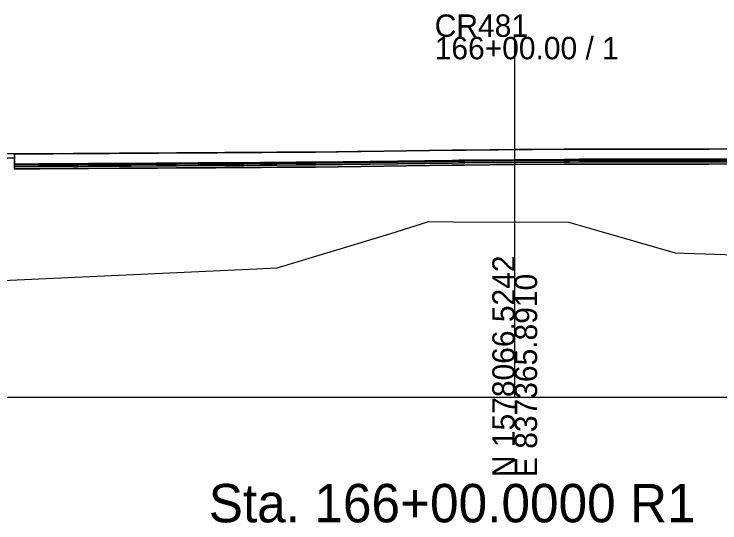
# Model space of a CAD drawing. Extents: x -26 to 303, y -16 to 6048.
# Drawn here: x 87.4 to 175.6, y 5984.3 to 6047.8 of the extents above; entities that cross this region are included whole.
import ezdxf

# ---------------------------------------------------------------- set-up
doc = ezdxf.new("R2010")
doc.units = 0
for name, color, linetype in [('ASPHALT_19MM1', 7, 'Continuous'), ('ASPHALT_9_5MM1', 7, 'Continuous'), ('CONST_LV3', 7, 'Continuous'), ('Default', 7, 'Continuous'), ('Draft_XS_Text', 7, 'Continuous'), ('DTM_P_FINISHED_GRADE', 7, 'Continuous'), ('DTM_P_FINISHED_GRADE2', 7, 'Continuous'), ('DTM_X_GROUND', 7, 'Continuous'), ('TRANS_PAVED_SHOULDERS', 7, 'Continuous'), ('XS_CELL', 7, 'Continuous'), ('XS_M_SHAPES_EARTHWORK', 7, 'Continuous'), ('XS_P_ASPHALT', 7, 'Continuous'), ('XS_P_SUBGRADE_GRANULAR', 7, 'Continuous')]:
    doc.layers.add(name, color=color, linetype=linetype)

msp = doc.modelspace()

# ---------------------------------------------------------------- linework, layer by layer
at = {"layer": 'ASPHALT_19MM1'}
for points in [[(90.504, 6028.792), (87.441, 6028.775), (87.441, 6028.504), (90.504, 6028.521), (90.558, 6028.522), (90.706, 6028.523), (94.869, 6028.545), (95.459, 6028.549), (96.738, 6028.558), (100.596, 6028.579), (102.069, 6028.589), (105.237, 6028.606), (105.365, 6028.607), (107.722, 6028.624), (110.43, 6028.639), (111.485, 6028.646), (111.83, 6028.649), (112.658, 6028.655), (113.784, 6028.663), (116.149, 6028.676), (118.218, 6028.692), (118.344, 6028.693), (120.279, 6028.703), (122.675, 6028.722), (122.886, 6028.723), (125.089, 6028.741), (142.197, 6028.968), (142.997, 6028.974), (143.099, 6028.975), (143.136, 6028.975), (143.744, 6028.98), (150, 6029.046), (156.166, 6029.08), (156.838, 6029.086), (158.11, 6029.096), (158.562, 6029.1), (159.52, 6029.106), (174.235, 6029.102), (176.786, 6029.125)], [(176.786, 6029.396), (174.235, 6029.373), (159.52, 6029.377), (158.562, 6029.371), (158.11, 6029.367), (156.838, 6029.356), (156.166, 6029.351), (150, 6029.316), (143.744, 6029.251), (143.136, 6029.246), (143.099, 6029.246), (142.997, 6029.245), (142.197, 6029.239), (125.089, 6029.011), (122.886, 6028.994), (122.675, 6028.993), (120.279, 6028.974), (118.344, 6028.964), (118.218, 6028.963), (116.149, 6028.947), (113.784, 6028.934), (112.658, 6028.926), (111.83, 6028.92), (111.485, 6028.917), (110.43, 6028.909), (107.722, 6028.895), (105.365, 6028.878), (105.237, 6028.877), (102.069, 6028.86), (100.596, 6028.849), (96.738, 6028.828), (95.459, 6028.82), (94.869, 6028.816), (90.706, 6028.793), (90.558, 6028.792), (90.504, 6028.792)]]:
    msp.add_lwpolyline(points, dxfattribs=at)
at = {"layer": 'ASPHALT_9_5MM1'}
for points in [[(90.504, 6029.125), (87.441, 6029.109), (87.441, 6028.984), (90.504, 6029), (90.558, 6029.001), (90.706, 6029.002), (94.869, 6029.024), (95.459, 6029.028), (96.738, 6029.037), (100.596, 6029.058), (102.069, 6029.068), (105.237, 6029.085), (105.365, 6029.086), (107.722, 6029.103), (110.43, 6029.118), (111.485, 6029.125), (111.83, 6029.128), (112.658, 6029.134), (113.784, 6029.143), (116.149, 6029.155), (118.218, 6029.171), (118.344, 6029.172), (120.279, 6029.182), (122.675, 6029.201), (122.886, 6029.203), (125.089, 6029.22), (142.197, 6029.447), (142.997, 6029.453), (143.099, 6029.454), (143.136, 6029.454), (143.744, 6029.459), (150, 6029.525), (156.166, 6029.559), (156.838, 6029.565), (158.11, 6029.576), (158.562, 6029.58), (159.52, 6029.586), (174.235, 6029.582), (176.786, 6029.605)], [(176.786, 6029.73), (174.235, 6029.707), (159.52, 6029.711), (158.562, 6029.705), (158.11, 6029.701), (156.838, 6029.69), (156.166, 6029.684), (150, 6029.65), (143.744, 6029.584), (143.136, 6029.579), (143.099, 6029.579), (142.997, 6029.578), (142.197, 6029.572), (125.089, 6029.345), (122.886, 6029.328), (122.675, 6029.326), (120.279, 6029.307), (118.344, 6029.297), (118.218, 6029.296), (116.149, 6029.28), (113.784, 6029.268), (112.658, 6029.259), (111.83, 6029.253), (111.485, 6029.25), (110.43, 6029.243), (107.722, 6029.228), (105.365, 6029.211), (105.237, 6029.21), (102.069, 6029.193), (100.596, 6029.183), (96.738, 6029.162), (95.459, 6029.153), (94.869, 6029.149), (90.706, 6029.127), (90.558, 6029.126), (90.504, 6029.125)]]:
    msp.add_lwpolyline(points, dxfattribs=at)
at = {"layer": 'CONST_LV3'}
for points in [[(176.786, 6031), (174.235, 6030.977), (159.52, 6030.981), (158.562, 6030.975), (158.11, 6030.971), (156.838, 6030.961), (156.166, 6030.955), (150, 6030.921), (143.744, 6030.855), (143.136, 6030.85), (143.099, 6030.85), (142.997, 6030.849), (142.197, 6030.843), (125.089, 6030.616), (122.886, 6030.598), (122.675, 6030.597), (120.279, 6030.578), (118.344, 6030.568), (118.218, 6030.567), (116.149, 6030.551), (113.784, 6030.538), (112.658, 6030.53), (111.83, 6030.524), (111.485, 6030.521), (110.43, 6030.514), (107.722, 6030.499), (105.365, 6030.482), (105.237, 6030.481), (102.069, 6030.464), (100.596, 6030.454), (96.738, 6030.433), (95.459, 6030.424), (94.869, 6030.42), (90.706, 6030.398), (90.558, 6030.397), (90.504, 6030.396)], [(85.645, 6029.871), (87.542, 6029.879), (87.542, 6030.379), (85.645, 6030.371)], [(90.504, 6030.396), (87.441, 6030.379), (87.441, 6029.109), (90.504, 6029.125), (90.558, 6029.126), (90.706, 6029.127), (94.869, 6029.149), (95.459, 6029.153), (96.738, 6029.162), (100.596, 6029.183), (102.069, 6029.193), (105.237, 6029.21), (105.365, 6029.211), (107.722, 6029.228), (110.43, 6029.243), (111.485, 6029.25), (111.83, 6029.253), (112.658, 6029.259), (113.784, 6029.268), (116.149, 6029.28), (118.218, 6029.296), (118.344, 6029.297), (120.279, 6029.307), (122.675, 6029.326), (122.886, 6029.328), (125.089, 6029.345), (142.197, 6029.572), (142.997, 6029.578), (143.099, 6029.579), (143.136, 6029.579), (143.744, 6029.584), (150, 6029.65), (156.166, 6029.684), (156.838, 6029.69), (158.11, 6029.701), (158.562, 6029.705), (159.52, 6029.711), (174.235, 6029.707), (176.786, 6029.73)]]:
    msp.add_lwpolyline(points, dxfattribs=at)
at = {"layer": 'Default'}
for points in [[(87.542, 6030.379), (87.745, 6030.38), (87.819, 6030.38), (90.048, 6030.394), (90.443, 6030.397), (90.459, 6030.397), (90.474, 6030.397), (90.599, 6030.397), (90.861, 6030.399), (91.006, 6030.399), (92.34, 6030.406), (93.426, 6030.412), (94.869, 6030.421), (95.463, 6030.425), (95.475, 6030.425), (95.58, 6030.425), (95.691, 6030.425), (96.854, 6030.431), (97.827, 6030.436), (99.347, 6030.447), (100.357, 6030.453), (100.367, 6030.453), (100.454, 6030.453), (102.194, 6030.465), (102.3, 6030.466), (102.982, 6030.47), (104.554, 6030.478), (105.244, 6030.483), (105.372, 6030.484), (105.456, 6030.483), (105.534, 6030.484), (108.837, 6030.508), (109.359, 6030.511), (109.788, 6030.513), (110.274, 6030.516), (111.486, 6030.523), (111.831, 6030.526), (111.839, 6030.526), (111.847, 6030.526), (111.915, 6030.525), (112.747, 6030.532), (112.822, 6030.532), (113.955, 6030.54), (114.332, 6030.542), (115.782, 6030.55), (116.154, 6030.553), (118.349, 6030.569), (118.356, 6030.569), (118.417, 6030.569), (118.481, 6030.57), (119.678, 6030.576), (119.964, 6030.577), (120.012, 6030.578), (122.122, 6030.594), (122.409, 6030.596), (122.675, 6030.598), (122.887, 6030.6), (122.944, 6030.599), (125.154, 6030.617), (125.21, 6030.617), (125.427, 6030.618), (129.568, 6030.674), (129.788, 6030.675), (129.793, 6030.676), (129.798, 6030.676), (129.844, 6030.676), (129.891, 6030.676), (130.054, 6030.677), (133.499, 6030.729), (134.843, 6030.747), (141.853, 6030.841), (142.405, 6030.846), (143.179, 6030.852), (143.279, 6030.853), (143.905, 6030.858), (147.923, 6030.9), (150, 6030.921), (152.201, 6030.934), (156.7, 6030.961), (157.949, 6030.972), (158.392, 6030.975), (158.855, 6030.978), (159.551, 6030.983), (159.652, 6030.983), (160.214, 6030.985), (169.681, 6030.981), (171.646, 6030.976), (171.648, 6030.976), (171.649, 6030.976), (171.649, 6030.976), (171.662, 6030.976), (171.715, 6030.977), (174.063, 6030.976), (174.224, 6030.978), (176.489, 6030.999)], [(176.786, 6029.125), (174.235, 6029.102), (159.52, 6029.106), (158.562, 6029.1), (158.11, 6029.096), (156.838, 6029.086), (156.166, 6029.08), (150, 6029.046), (143.744, 6028.98), (143.136, 6028.975), (143.099, 6028.975), (142.997, 6028.974), (142.197, 6028.968), (125.089, 6028.741), (122.886, 6028.723), (122.675, 6028.722), (120.279, 6028.703), (118.344, 6028.693), (118.218, 6028.692), (116.149, 6028.676), (113.784, 6028.663), (112.658, 6028.655), (111.83, 6028.649), (111.485, 6028.646), (110.43, 6028.639), (107.722, 6028.624), (105.365, 6028.607), (105.237, 6028.606), (102.069, 6028.589), (100.596, 6028.579), (96.738, 6028.558), (95.459, 6028.549), (94.869, 6028.545), (90.706, 6028.523), (90.558, 6028.522), (90.504, 6028.521), (87.542, 6028.505), (87.542, 6030.379), (87.745, 6030.38), (87.819, 6030.38), (90.048, 6030.394), (90.443, 6030.397), (90.459, 6030.397), (90.474, 6030.397), (90.599, 6030.397), (90.861, 6030.399), (91.006, 6030.399), (92.34, 6030.406), (93.426, 6030.412), (94.869, 6030.421), (95.463, 6030.425), (95.475, 6030.425), (95.58, 6030.425), (95.691, 6030.425), (96.854, 6030.431), (97.827, 6030.436), (99.347, 6030.447), (100.357, 6030.453), (100.367, 6030.453), (100.454, 6030.453), (102.194, 6030.465), (102.3, 6030.466), (102.982, 6030.47), (104.554, 6030.478), (105.244, 6030.483), (105.372, 6030.484), (105.456, 6030.483), (105.534, 6030.484), (108.837, 6030.508), (109.359, 6030.511), (109.788, 6030.513), (110.274, 6030.516), (111.486, 6030.523), (111.831, 6030.526), (111.839, 6030.526), (111.847, 6030.526), (111.915, 6030.525), (112.747, 6030.532), (112.822, 6030.532), (113.955, 6030.54), (114.332, 6030.542), (115.782, 6030.55), (116.154, 6030.553), (118.349, 6030.569), (118.356, 6030.569), (118.417, 6030.569), (118.481, 6030.57), (119.678, 6030.576), (119.964, 6030.577), (120.012, 6030.578), (122.122, 6030.594), (122.409, 6030.596), (122.675, 6030.598), (122.887, 6030.6), (122.944, 6030.599), (125.154, 6030.617), (125.21, 6030.617), (125.427, 6030.618), (129.568, 6030.674), (129.788, 6030.675), (129.793, 6030.676), (129.798, 6030.676), (129.844, 6030.676), (129.891, 6030.676), (130.054, 6030.677), (133.499, 6030.729), (134.843, 6030.747), (141.853, 6030.841), (142.405, 6030.846), (143.179, 6030.852), (143.279, 6030.853), (143.905, 6030.858), (147.923, 6030.9), (150, 6030.921), (152.201, 6030.934), (156.7, 6030.961), (157.949, 6030.972), (158.392, 6030.975), (158.855, 6030.978), (159.551, 6030.983), (159.652, 6030.983), (160.214, 6030.985), (169.681, 6030.981), (171.646, 6030.976), (171.648, 6030.976), (171.649, 6030.976), (171.662, 6030.976), (171.715, 6030.977), (174.063, 6030.976), (174.224, 6030.978), (176.489, 6030.999)]]:
    msp.add_lwpolyline(points, dxfattribs=at)
at = {"layer": 'DTM_P_FINISHED_GRADE'}
msp.add_lwpolyline([(87.441, 6030.379), (90.504, 6030.396), (90.558, 6030.397), (90.706, 6030.398), (94.869, 6030.42), (95.459, 6030.424), (96.738, 6030.433), (100.596, 6030.454), (102.069, 6030.464), (105.237, 6030.481), (105.365, 6030.482), (107.722, 6030.499), (110.43, 6030.514), (111.485, 6030.521), (111.83, 6030.524), (112.658, 6030.53), (113.784, 6030.538), (116.149, 6030.551), (118.218, 6030.567), (118.344, 6030.568), (120.279, 6030.578), (122.675, 6030.597), (122.886, 6030.598), (125.089, 6030.616), (142.197, 6030.843), (142.997, 6030.849), (143.099, 6030.85), (143.136, 6030.85), (143.744, 6030.855), (150, 6030.921), (156.166, 6030.955), (156.838, 6030.961), (158.11, 6030.971), (158.562, 6030.975), (159.52, 6030.981), (174.235, 6030.977), (176.786, 6031)], dxfattribs=at)
at = {"layer": 'DTM_P_FINISHED_GRADE2'}
msp.add_lwpolyline([(87.441, 6030.379), (90.504, 6030.396), (90.706, 6030.398), (94.869, 6030.42), (95.459, 6030.424), (98.701, 6030.44), (102.069, 6030.464), (105.237, 6030.481), (105.365, 6030.482), (108.628, 6030.506), (111.485, 6030.522), (111.83, 6030.524), (112.658, 6030.531), (113.784, 6030.539), (116.149, 6030.552), (118.344, 6030.569), (120.279, 6030.579), (122.675, 6030.598), (122.886, 6030.599), (125.089, 6030.616), (142.197, 6030.843), (142.997, 6030.85), (143.099, 6030.85), (143.744, 6030.855), (150, 6030.921), (156.838, 6030.961), (158.11, 6030.972), (158.562, 6030.976), (159.52, 6030.982), (174.235, 6030.978), (176.786, 6031.001)], dxfattribs=at)
at = {"layer": 'DTM_X_GROUND'}
for points in [[(87.441, 6030.379), (90.504, 6030.396), (90.706, 6030.398), (94.869, 6030.42), (95.459, 6030.424), (98.701, 6030.44), (102.069, 6030.464), (105.237, 6030.481), (105.365, 6030.482), (108.628, 6030.506), (111.485, 6030.522), (111.83, 6030.524), (112.658, 6030.531), (113.784, 6030.539), (116.149, 6030.552), (118.344, 6030.569), (120.279, 6030.579), (122.675, 6030.598), (122.886, 6030.599), (125.089, 6030.616), (142.197, 6030.843), (142.997, 6030.85), (143.099, 6030.85), (143.744, 6030.855), (150, 6030.921), (156.838, 6030.961), (158.11, 6030.972), (158.562, 6030.976), (159.52, 6030.982), (174.235, 6030.978), (176.786, 6031.001)], [(83.233, 6014.422), (116.875, 6015.983), (120.32, 6016.154), (134.405, 6020.411), (139.253, 6021.933), (142.32, 6021.886), (156.706, 6021.83), (160.205, 6020.86), (170.026, 6018.017), (171.216, 6017.975), (172.522, 6017.929), (178.732, 6017.709), (183.508, 6017.541), (203.983, 6016.931), (211.237, 6016.67), (218.725, 6016.4), (221.804, 6016.289), (230.273, 6016.114)]]:
    msp.add_lwpolyline(points, dxfattribs=at)
at = {"layer": 'TRANS_PAVED_SHOULDERS'}
for points in [[(90.504, 6029), (87.441, 6028.984), (87.441, 6028.775), (90.504, 6028.792), (90.558, 6028.792), (90.706, 6028.793), (94.869, 6028.816), (95.459, 6028.82), (96.738, 6028.828), (100.596, 6028.849), (102.069, 6028.86), (105.237, 6028.877), (105.365, 6028.878), (107.722, 6028.895), (110.43, 6028.909), (111.485, 6028.917), (111.83, 6028.92), (112.658, 6028.926), (113.784, 6028.934), (116.149, 6028.947), (118.218, 6028.963), (118.344, 6028.964), (120.279, 6028.974), (122.675, 6028.993), (122.886, 6028.994), (125.089, 6029.011), (142.197, 6029.239), (142.997, 6029.245), (143.099, 6029.246), (143.136, 6029.246), (143.744, 6029.251), (150, 6029.316), (156.166, 6029.351), (156.838, 6029.356), (158.11, 6029.367), (158.562, 6029.371), (159.52, 6029.377), (174.235, 6029.373), (176.786, 6029.396)], [(176.786, 6029.605), (174.235, 6029.582), (159.52, 6029.586), (158.562, 6029.58), (158.11, 6029.576), (156.838, 6029.565), (156.166, 6029.559), (150, 6029.525), (143.744, 6029.459), (143.136, 6029.454), (143.099, 6029.454), (142.997, 6029.453), (142.197, 6029.447), (125.089, 6029.22), (122.886, 6029.203), (122.675, 6029.201), (120.279, 6029.182), (118.344, 6029.172), (118.218, 6029.171), (116.149, 6029.155), (113.784, 6029.143), (112.658, 6029.134), (111.83, 6029.128), (111.485, 6029.125), (110.43, 6029.118), (107.722, 6029.103), (105.365, 6029.086), (105.237, 6029.085), (102.069, 6029.068), (100.596, 6029.058), (96.738, 6029.037), (95.459, 6029.028), (94.869, 6029.024), (90.706, 6029.002), (90.558, 6029.001), (90.504, 6029)]]:
    msp.add_lwpolyline(points, dxfattribs=at)
at = {"layer": 'XS_CELL'}
for p, q in [((150, 6000), (150, 6045)), ((0, 6000), (150, 6000)), ((150, 6000), (300, 6000))]:
    msp.add_line(p, q, dxfattribs=at)
at = {"layer": 'XS_M_SHAPES_EARTHWORK'}
for points in [[(132.95, 6030.721), (125.095, 6030.616), (125.154, 6030.617), (125.21, 6030.617), (125.427, 6030.618), (129.568, 6030.674), (129.788, 6030.675), (129.793, 6030.676), (129.798, 6030.676), (129.844, 6030.676), (129.891, 6030.676), (130.054, 6030.677)], [(174.219, 6030.978), (170.359, 6030.979), (171.646, 6030.976), (171.648, 6030.976), (171.649, 6030.976), (171.662, 6030.976), (171.715, 6030.977), (174.063, 6030.976)], [(93.617, 6030.413), (91.73, 6030.403), (92.34, 6030.406), (93.426, 6030.412)], [(124.662, 6030.613), (122.928, 6030.599), (122.944, 6030.599)]]:
    msp.add_lwpolyline(points, close=True, dxfattribs=at)
msp.add_lwpolyline([(87.441, 6029.109), (87.441, 6028.984), (87.441, 6028.775), (87.441, 6028.504), (87.542, 6028.505), (87.542, 6030.379), (87.745, 6030.38), (87.819, 6030.38), (89.151, 6030.389), (87.441, 6030.379)], dxfattribs=at)
at = {"layer": 'XS_P_ASPHALT'}
msp.add_lwpolyline([(176.786, 6031), (174.235, 6030.977), (159.52, 6030.981), (158.562, 6030.975), (158.11, 6030.971), (156.838, 6030.961), (156.166, 6030.955), (150, 6030.921), (143.744, 6030.855), (143.136, 6030.85), (143.099, 6030.85), (142.997, 6030.849), (142.197, 6030.843), (125.089, 6030.616), (122.886, 6030.598), (122.675, 6030.597), (120.279, 6030.578), (118.344, 6030.568), (118.218, 6030.567), (116.149, 6030.551), (113.784, 6030.538), (112.658, 6030.53), (111.83, 6030.524), (111.485, 6030.521), (110.43, 6030.514), (107.722, 6030.499), (105.365, 6030.482), (105.237, 6030.481), (102.069, 6030.464), (100.596, 6030.454), (96.738, 6030.433), (95.459, 6030.424), (94.869, 6030.42), (90.706, 6030.398), (90.558, 6030.397), (90.504, 6030.396), (87.441, 6030.379)], dxfattribs=at)
at = {"layer": 'XS_P_SUBGRADE_GRANULAR'}
msp.add_lwpolyline([(176.786, 6029.73), (174.235, 6029.707), (159.52, 6029.711), (158.562, 6029.705), (158.11, 6029.701), (156.838, 6029.69), (156.166, 6029.684), (150, 6029.65), (143.744, 6029.584), (143.136, 6029.579), (143.099, 6029.579), (142.997, 6029.578), (142.197, 6029.572), (125.089, 6029.345), (122.886, 6029.328), (122.675, 6029.326), (120.279, 6029.307), (118.344, 6029.297), (118.218, 6029.296), (116.149, 6029.28), (113.784, 6029.268), (112.658, 6029.259), (111.83, 6029.253), (111.485, 6029.25), (110.43, 6029.243), (107.722, 6029.228), (105.365, 6029.211), (105.237, 6029.21), (102.069, 6029.193), (100.596, 6029.183), (96.738, 6029.162), (95.459, 6029.153), (94.869, 6029.149), (90.706, 6029.127), (90.558, 6029.126), (90.504, 6029.125), (87.441, 6029.109)], dxfattribs=at)

# ---------------------------------------------------------------- texts
at = {"layer": 'Draft_XS_Text'}
msp.add_text('Sta. 166+00.0000 R1', height=4.8, dxfattribs=at).set_placement((111.754, 5984.35))
at = {"layer": 'XS_CELL'}
for s, p in [('CR481', (140, 6045)), ('166+00.00 / 1', (140, 6042.2))]:
    msp.add_text(s, height=2.8, dxfattribs=at).set_placement(p)
for s, p in [('N 1578066.5242', (150, 5990)), ('E 837365.8910', (152.8, 5990))]:
    msp.add_text(s, height=2.8, rotation=90, dxfattribs=at).set_placement(p)

doc.saveas('drawing.dxf')
